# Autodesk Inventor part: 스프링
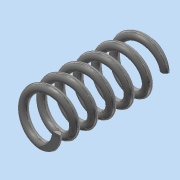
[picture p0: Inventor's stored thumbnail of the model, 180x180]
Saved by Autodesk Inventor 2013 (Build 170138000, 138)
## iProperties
Created: 2015-12
Part Number: 스프링
Material: 강철, 탄소
Document SubType Name: Modeling
Designer: Administrator
Density: 7.87 g/cm^3
Mass: 16.513 g
Surface Area: 28.4714 cm^2
Volume: 2.09823 cm^3
Author: Administrator
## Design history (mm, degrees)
sketch "스케치1"
  geometry: L1 (0, 0)-(0, 42); L2 (0, 0)-(8, 0); L3 (0, 42)-(8, 42); C1 r 1.5 at (8, 0); 1 further point
  constraints: 6 end point, 1 centre point, 1 coincident, 1 horizontal alignment, 1 parallel, 1 perpendicular, 1 vertical
  dimensions: "d0" = 42 distance of L1.start L1.end (derived); "d1" = 3 diameter of C1; "d2" = 16 diameter of L2.end L1; "d3" = 8 distance of L1.end L3.end
feature "코일1" sketch "스케치1" pitch "d4" = 10; turns "d6" = 6; dims "d5" = 42 (= d0), "d7" = 0, angle "d8" = 90 deg, angle "d9" = 90 deg, "d10" = 0, "d11" = 0
sketch "스케치2"
  geometry: L1 (42, 18.366)-(0, 18.366); L2 (0, 18.366)-(0, -15.947); L3 (0, -15.947)-(42, -15.947); L4 (42, -15.947)-(42, 18.366); 1 further point
  constraints: 8 end point, 2 parallel, 1 horizontal, 1 perpendicular, 1 point on line
  dimensions: "d12" = 42 distance of L1.start L1.end (derived)
extrude "돌출1" sketch "스케치2" stored distance "d14" = 10; taper "d15" = 0 deg
node "솔리드1"
